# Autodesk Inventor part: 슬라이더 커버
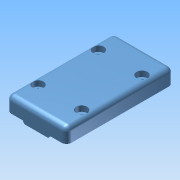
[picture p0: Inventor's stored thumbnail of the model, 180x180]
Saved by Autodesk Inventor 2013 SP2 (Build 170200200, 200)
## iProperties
Created: 2025-07
Part Number: 슬라이더 커버
Material: Generic
Document SubType Name: Modeling
Designer: a
Density: 1 g/cm^3
Author: a
변환 표준: STEP AP214IS
전처리기: Build: 200, Release: 2013 SP2 Update 6 - Date: Thu 07/17/2014
전송 단위: 밀리미터
불확실성: 0.01
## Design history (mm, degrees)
node "슬라이더 커버1"
node "솔리드1"
node "기준1"
